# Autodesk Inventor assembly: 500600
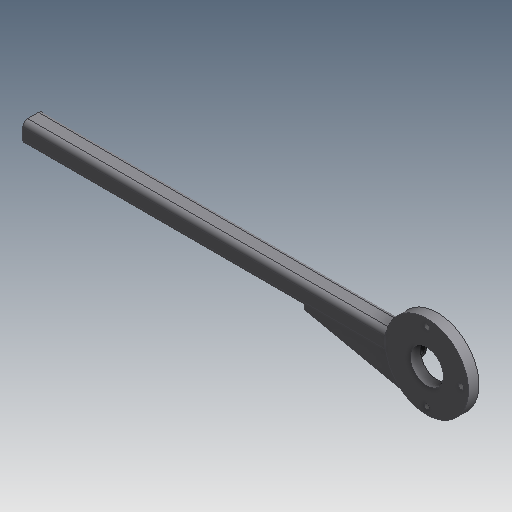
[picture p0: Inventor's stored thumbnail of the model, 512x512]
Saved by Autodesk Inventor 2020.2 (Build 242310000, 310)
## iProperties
Created: 2000-02
Part Number: 500600
Document SubType Name: Assembly
Designer: sspink
Mass: 1581.72 g
Surface Area: 983.046 cm^2
Volume: 202.008 cm^3
Density: 7.83 g/cm^3
Control State: 0
Checked Out: False
Master: False
Shininess: 0.0
Length Units: 11269
Angle Units: 11279
Time Units: 11290
Mass Units: 11283
Length Display Precision: 3
Angle Display Precision: 2
Compacted: True
Dimensions: 100x25x535,4 mm
Mass: 1,582 kg
DocNumber: 500600.iam
Folder: 01 - Themengebiete\Simplification\01 - Packaging machine\
VDS_Category: 3D Komponenten
Density: 0.0
Volumn: 0.0
Area: 0.0
PropertySet Name: Model Information
Author: sspink
Revision Number: -
Title: 500600
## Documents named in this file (5)
- D:\07 - DEMODATEN\OTX 2019 - Dataset - UPDATE - Dez2019\Designs\07-Packing machine\500600.iam
- D:\07 - DEMODATEN\OTX 2019 - Dataset - UPDATE - Dez2019\Designs\07-Packing machine\Parts\ADSK-011562.ipt
- D:\07 - DEMODATEN\OTX 2019 - Dataset - UPDATE - Dez2019\Designs\07-Packing machine\Parts\ADSK-011561.ipt
- D:\07 - DEMODATEN\OTX 2019 - Dataset - UPDATE - Dez2019\Designs\07-Packing machine\Parts\ADSK-011563.ipt
- D:\07 - DEMODATEN\OTX 2019 - Dataset - UPDATE - Dez2019\Designs\07-Packing machine\Parts\ADSK-011727.ipt
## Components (4 placed, 4 different names)
1. ADSK-011561:1 — Mate:1, Flush:1, Mate:2
2. ADSK-011562:1 — Mate:1, Flush:1, Mate:3
3. ADSK-011563:1 — Mate:2, Mate:3, Flush:2, Mate:4, Mate:5
4. ADSK-011727:1 — Mate:4, Mate:5
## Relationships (7: Mate 5, Flush 2)
- Mate:1: ADSK-011561:1 ↔ ADSK-011562:1
- Flush:1: ADSK-011561:1 ↔ ADSK-011562:1
- Mate:2: ADSK-011561:1 ↔ ADSK-011563:1
- Mate:3: ADSK-011562:1 ↔ ADSK-011563:1
- Flush:2: ADSK-011563:1
- Mate:4: ADSK-011563:1 ↔ ADSK-011727:1
- Mate:5: ADSK-011563:1 ↔ ADSK-011727:1
